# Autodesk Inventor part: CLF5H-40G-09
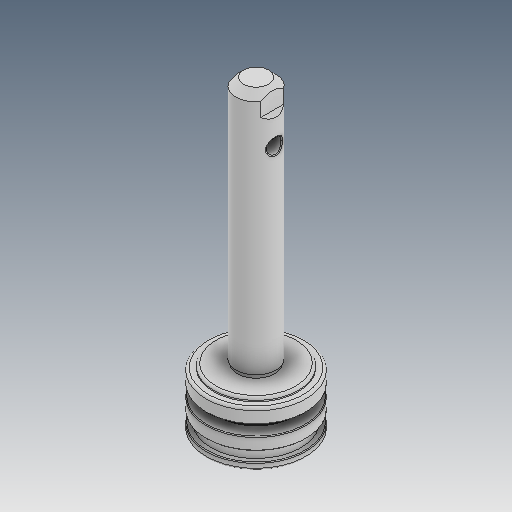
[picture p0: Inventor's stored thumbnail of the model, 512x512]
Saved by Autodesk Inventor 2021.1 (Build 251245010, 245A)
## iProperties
Created: 2013-04
Part Number: CLF5H-40G-09
Material: Ogólny
Document SubType Name: Modeling
Designer: user
Density: 1 g/cm^3
Appearance: Domyślna
Author: user
Revision Number: ÈÎºÎ
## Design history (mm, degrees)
feature "µ¹½Ç2"
node "Bryła1"
